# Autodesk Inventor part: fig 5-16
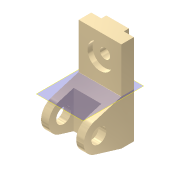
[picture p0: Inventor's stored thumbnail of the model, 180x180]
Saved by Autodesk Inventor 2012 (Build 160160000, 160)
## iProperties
Shininess: 65.0
Angle Display Precision: 2
Document Length Units: 11269
Document Angle Units: 11279
Document Time Units: 11290
Document Mass Units: 11283
Document Length Units Precision: 3
Document Angle Units Precision: 2
Compacted: False
Created: 2001-11
Part Number: fig 5-16
Document SubType Name: Modeling
Designer: Renu Muthoo
Density: 1 g/cm^3
Material: Default
Density: 0.0
Volumn: 0.0
Area: 0.0
PropertySet Name: Model Information
Control State: 0
Master: False
Checked Out: False
Author: Renu Muthoo
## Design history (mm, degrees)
node "Sketch1"
sketch "Sketch2"
  geometry: L1 (33.257, 104.664)-(33.257, -75.336); L2 (33.257, -75.336)-(8.257, -75.336); L3 (8.257, -75.336)-(-45.451, -59.045); L4 (-45.451, -1.628)-(8.257, 14.664); L5 (8.257, 14.664)-(8.257, 104.664); L6 (8.257, 104.664)-(33.257, 104.664); C1 r 15 at (-36.743, -30.336); A1 r 30 centre (-36.743, -30.336) between (-45.451, -1.628) and (-45.451, -59.045)
  constraints: 12 end point, 2 centre point, 2 equal length, 2 parallel, 2 point on circle, 2 tangent, 1 coincident, 1 perpendicular, 1 vertical
  dimensions: "d0" = 180 distance of L1.start L1.end; "d1" = 30 radius of A1; "d2" = 25 distance of L5.end L1.start; "d3" = 45 distance from line of L2 A1.centre; "d4" = 70 distance from line of L1 A1.centre; "d5" = 30 diameter of C1
extrude "Extrusion1" new body sketch "Sketch2" distance "d6" = 85; taper "d7" = 0 deg
workplane "Work Plane1"
sketch "Sketch3"
  geometry: L1 (15, 62.364)-(70, 62.364); L2 (70, 62.364)-(70, -52.386); L3 (70, -52.386)-(15, -52.386); L4 (15, -52.386)-(15, 62.364); L5 (0, -45)-(0, -28.708) reference
  constraints: 8 end point, 2 parallel, 1 horizontal, 1 perpendicular
  dimensions: "d8" = 55 distance of L1.start L1.end; "d9" = 15 distance between parallel lines of L5 L4
extrude "Extrusion2" cut sketch "Sketch3" distance "d10" = 50; taper "d11" = 0 deg
sketch "Sketch4"
  geometry: L1 (0, 25)-(85, 25) reference; L2 (0, 0)-(0, 25) reference; L3 (20, 25)-(65, 25); L4 (65, 25)-(65, 35); L5 (65, 35)-(20, 35); L6 (20, 35)-(20, 25)
  constraints: 8 end point, 2 parallel, 1 horizontal, 1 perpendicular, 1 point on line
  dimensions: "d12" = 45 distance of L4.end L5.end; "d13" = 10 distance of L3.end L4.end; "d14" = 20 distance between parallel lines of L2 L6
extrude "Extrusion3" join sketch "Sketch4" stored distance "d15" = 50; taper "d16" = 0 deg
sketch "Sketch5"
  geometry: L1 (85, 0)-(85, 90) reference; L2 (0, 90)-(85, 90) reference; 1 further point
  dimensions: "d17" = 42 distance from line of L2 point (42.5, 48); "d18" = 42.5 distance from line of L1 point (42.5, 48)
hole "Hole1" sketch "Sketch5" at (42.5, 48) diameter "d19" = 20; stored, may be unused: countersink angle "d23" = 82 deg, drill point angle "d25" = 118 deg; dims "d20" = 6, "d21" = 50, "d22" = 10, "d24" = 8
workplane "Work Plane7"
body "Solid1"
other parameters: "d27" = 90 deg
